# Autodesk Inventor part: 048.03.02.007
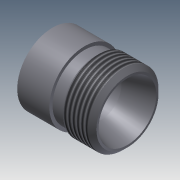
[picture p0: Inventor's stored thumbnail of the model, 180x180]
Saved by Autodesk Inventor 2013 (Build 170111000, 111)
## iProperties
Shininess: 25.0
Angle Display Precision: 2
Document Length Units: 11269
Document Angle Units: 11279
Document Time Units: 11290
Document Mass Units: 11283
Document Length Units Precision: 3
Document Angle Units Precision: 2
Created: 2002-04
Part Number: 048.03.02.007
Material: Steel, Mild
Document SubType Name: Modeling
Designer: SaAlex
Density: 7.86 g/cm^3
Density: 0.0
Volumn: 0.0
Area: 0.0
PropertySet Name: Model Information
Control State: 0
Master: False
Checked Out: True
Checked Out Date: 2008-10-15
Last Check In Date: 2008-10-15
Title: Штуцер
Author: SaAlex
Comments: 048.03.02.007
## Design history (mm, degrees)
sketch "Sketch2"
  geometry: L1 (0, 0)-(35, 0) reference; L2 (35, 0)-(35, -9.5); L3 (35, -9.5)-(12.311, -9.5); L4 (12.311, -9.5)-(0, -13.5); L5 (0, -13.5)-(0, 0); L6 (35, 16.5)-(35, -16.5) reference; L7 (0, 14.5)-(0, -14.5) reference
  constraints: 10 end point, 2 horizontal, 2 parallel, 1 perpendicular
  dimensions: "d7" = 9.5 distance of L1.end L2.end; "d8" = 0 distance between parallel lines of L6 L2; "d9" = 0 distance between parallel lines of L7 L5; "d10" = 18 deg angle of L3 L4; "d13" = 13.5 distance from line of L4.end L1
sketch "Sketch3"
  geometry: C1 r 9.5 at (0, 0) reference; C2 r 16.5 at (0, 0) reference; C3 r 13 at (0, 0)
  constraints: 1 centre point, 1 coincident
  dimensions: "d14" = 26 diameter of C3
body "Solid1"
revolve "Revolution1" stored, may be unused: angle "d6" = 90 deg
revolve "Revolution2" stored, may be unused: angle "d12" = 90 deg
extrude "Extrusion1" cut sketch "Sketch3" distance "d15" = 5; taper "d16" = 0 deg
thread "Thread1" dims "d17" = 10, "d18" = 0
sketch "Sketch1"
  geometry: L1 (0, 0)-(-35, 0) reference; L2 (-35, 0)-(-35, 16.5); L3 (-35, 16.5)-(-20, 16.5); L4 (-20, 16.5)-(-20, 15); L5 (-20, 15)-(-15, 15); L6 (-15, 15)-(-13.5, 16.5); L7 (-13.5, 16.5)-(-2, 16.5); L8 (-2, 16.5)-(0, 14.5); L9 (0, 14.5)-(0, 0)
  constraints: 18 end point, 3 perpendicular, 2 horizontal, 2 parallel, 2 point on line
  dimensions: "d0" = 35 distance of L1.start L1.end; "d1" = 2 horizontal distance of L7.end L8.end; "d2" = 45 deg angle of L7 L8; "d3" = 45 deg angle of L5 L6; "d4" = 15 distance between parallel lines of L1 L5; "d5" = 16.5 distance of L1.end L2.end; "d19" = 20 distance from line of L3.end L9; "d20" = 5 distance of L4.end L5.end
